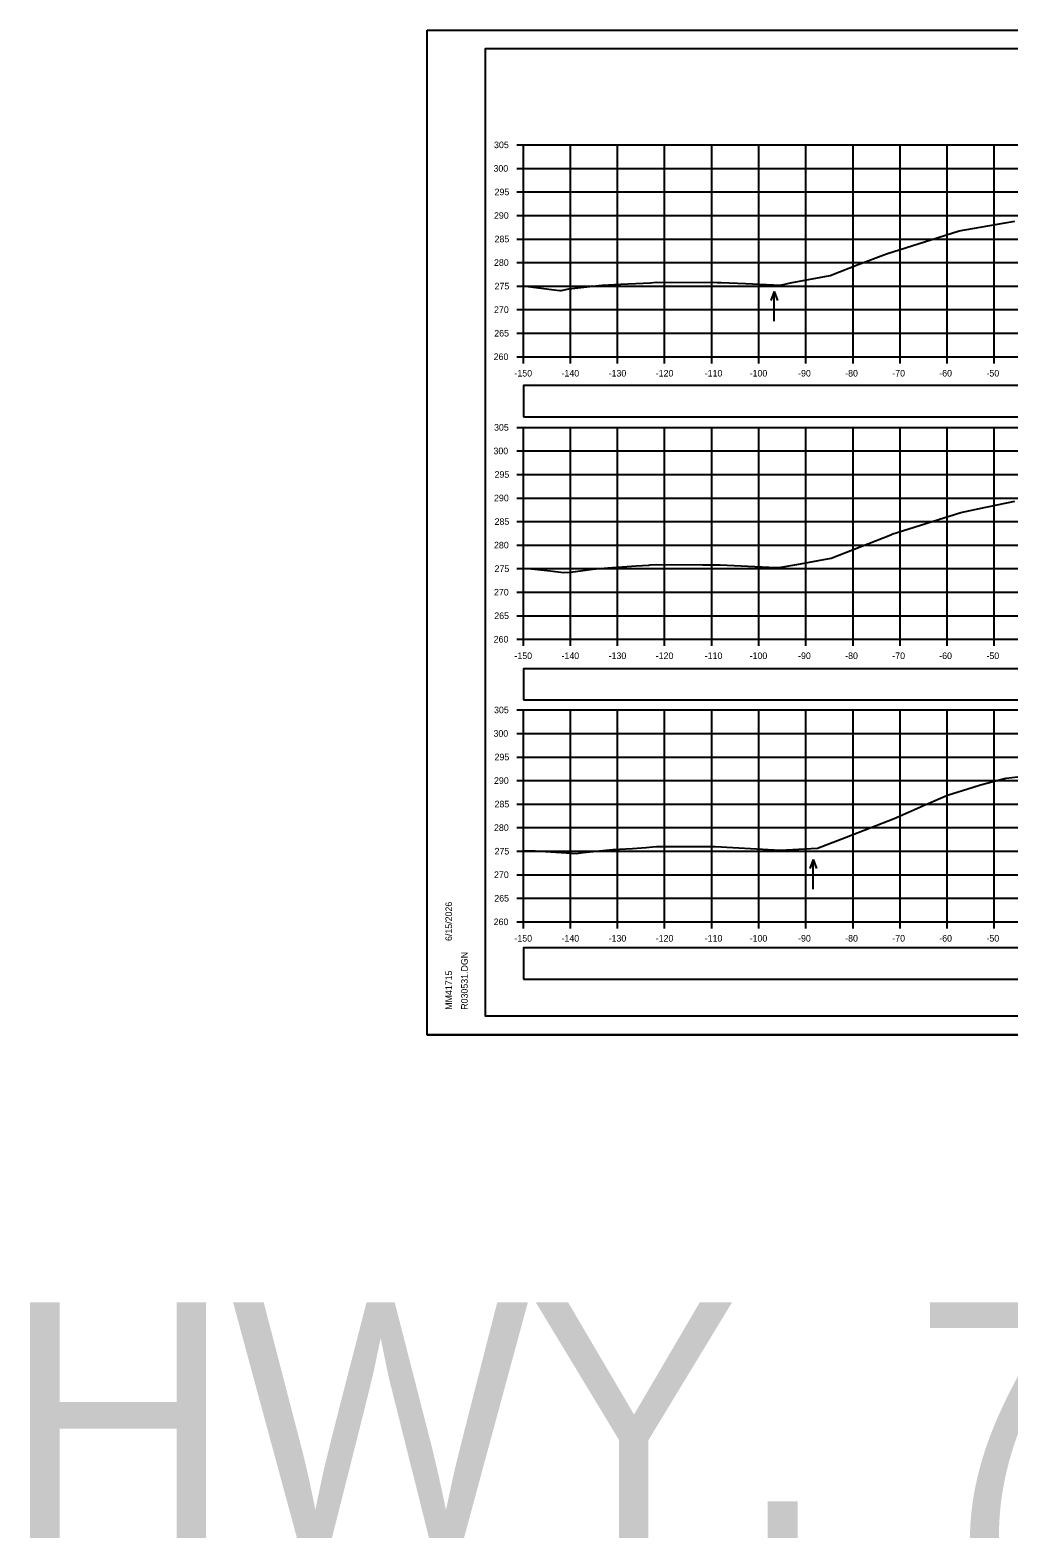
# Model space of a CAD drawing. Extents: x 285 to 4233, y -659 to 3710.
# Drawn here: x 284.6 to 492.4, y -130.7 to 189.5 of the extents above; entities that cross this region are included whole.
import ezdxf

# ---------------------------------------------------------------- set-up
doc = ezdxf.new("R2010")
doc.units = 0
for name, color, linetype in [('R_Axis', 7, 'Continuous'), ('R_Axis Annot', 7, 'Continuous'), ('R_Border', 7, 'Continuous'), ('R_Exist Surface', 7, 'Continuous'), ('R_Grid', 7, 'Continuous'), ('R_No Plot', 7, 'Continuous'), ('R_Water Annot', 7, 'Continuous')]:
    doc.layers.add(name, color=color, linetype=linetype)

msp = doc.modelspace()

# ---------------------------------------------------------------- linework, layer by layer
at = {"layer": 'R_Axis'}
for p, q in [((387.88, 165.15), (389.28, 165.15)), ((389.28, 120.15), (389.28, 165.15)), ((387.88, 160.15), (389.28, 160.15)), ((387.88, 155.15), (389.28, 155.15)), ((387.88, 150.15), (389.28, 150.15)), ((387.88, 145.15), (389.28, 145.15)), ((387.88, 140.15), (389.28, 140.15)), ((387.88, 135.15), (389.28, 135.15)), ((387.88, 130.15), (389.28, 130.15)), ((387.88, 125.15), (389.28, 125.15)), ((387.88, 120.15), (389.28, 120.15)), ((389.28, 120.15), (689.28, 120.15)), ((389.28, 118.75), (389.28, 120.15)), ((399.28, 118.75), (399.28, 120.15)), ((409.28, 118.75), (409.28, 120.15)), ((419.28, 118.75), (419.28, 120.15)), ((429.28, 118.75), (429.28, 120.15)), ((439.28, 118.75), (439.28, 120.15)), ((449.28, 118.75), (449.28, 120.15)), ((459.28, 118.75), (459.28, 120.15)), ((469.28, 118.75), (469.28, 120.15)), ((479.28, 118.75), (479.28, 120.15)), ((489.28, 118.75), (489.28, 120.15)), ((387.88, 105.15), (389.28, 105.15)), ((389.28, 60.15), (389.28, 105.15)), ((387.88, 100.15), (389.28, 100.15)), ((387.88, 95.15), (389.28, 95.15)), ((387.88, 90.15), (389.28, 90.15)), ((387.88, 85.15), (389.28, 85.15)), ((387.88, 80.15), (389.28, 80.15)), ((387.88, 75.15), (389.28, 75.15)), ((387.88, 70.15), (389.28, 70.15)), ((387.88, 65.15), (389.28, 65.15)), ((387.88, 60.15), (389.28, 60.15)), ((389.28, 60.15), (689.28, 60.15)), ((389.28, 58.75), (389.28, 60.15)), ((399.28, 58.75), (399.28, 60.15)), ((409.28, 58.75), (409.28, 60.15)), ((419.28, 58.75), (419.28, 60.15)), ((429.28, 58.75), (429.28, 60.15)), ((439.28, 58.75), (439.28, 60.15)), ((449.28, 58.75), (449.28, 60.15)), ((459.28, 58.75), (459.28, 60.15)), ((469.28, 58.75), (469.28, 60.15)), ((479.28, 58.75), (479.28, 60.15)), ((489.28, 58.75), (489.28, 60.15)), ((387.88, 45.15), (389.28, 45.15)), ((389.28, 0.15), (389.28, 45.15)), ((387.88, 40.15), (389.28, 40.15)), ((387.88, 35.15), (389.28, 35.15)), ((387.88, 30.15), (389.28, 30.15)), ((387.88, 25.15), (389.28, 25.15)), ((387.88, 20.15), (389.28, 20.15)), ((387.88, 15.15), (389.28, 15.15)), ((387.88, 10.15), (389.28, 10.15)), ((387.88, 5.15), (389.28, 5.15)), ((387.88, 0.15), (389.28, 0.15)), ((389.28, 0.15), (689.28, 0.15)), ((389.28, -1.25), (389.28, 0.15)), ((399.28, -1.25), (399.28, 0.15)), ((409.28, -1.25), (409.28, 0.15)), ((419.28, -1.25), (419.28, 0.15)), ((429.28, -1.25), (429.28, 0.15)), ((439.28, -1.25), (439.28, 0.15)), ((449.28, -1.25), (449.28, 0.15)), ((459.28, -1.25), (459.28, 0.15)), ((469.28, -1.25), (469.28, 0.15)), ((479.28, -1.25), (479.28, 0.15)), ((489.28, -1.25), (489.28, 0.15))]:
    msp.add_line(p, q, dxfattribs=at)
at = {"layer": 'R_Axis Annot'}
for points in [[(389.28, 107.36), (516.61, 107.36), (516.61, 114.02), (389.28, 114.02)], [(389.28, 47.26), (516.61, 47.26), (516.61, 53.91), (389.28, 53.91)], [(389.28, -12.05), (516.61, -12.05), (516.61, -5.4), (389.28, -5.4)]]:
    msp.add_lwpolyline(points, close=True, dxfattribs=at)
at = {"layer": 'R_Border'}
for p, q in [((381.28, 185.61), (697.46, 185.61)), ((381.28, -19.85), (381.28, 185.61)), ((381.28, -19.85), (381.28, -19.85)), ((697.46, -19.85), (381.28, -19.85))]:
    msp.add_line(p, q, dxfattribs=at)
at = {"layer": 'R_Exist Surface'}
for points in [[(389.28, 135.14), (389.71, 135.13), (395.79, 134.36), (397.03, 134.22), (397.31, 134.25), (398.95, 134.57), (405.32, 135.28), (406.02, 135.36), (409.99, 135.57), (416.31, 135.88), (417.45, 135.96), (430.46, 135.93), (431.32, 135.93), (436.44, 135.71), (443.87, 135.37), (446.03, 135.82), (454.41, 137.41), (460.4, 139.72), (466.37, 142), (477.33, 145.48), (481.85, 146.88), (491.13, 148.52), (493.61, 148.96)], [(389.28, 75.26), (390.41, 75.21), (395, 74.68), (397.84, 74.31), (399.23, 74.43), (400.35, 74.57), (403.96, 75.01), (407.2, 75.34), (413.23, 75.74), (415.93, 75.9), (416.2, 75.93), (417.5, 76.01), (427.42, 75.99), (431.1, 75.99), (441.41, 75.49), (443.58, 75.37), (447.37, 76.04), (454.65, 77.38), (467.32, 82.36), (467.45, 82.42), (467.52, 82.44), (482.21, 87.06), (486.17, 87.92), (493.65, 89.45)], [(389.28, 15.2), (391.79, 15.19), (398.38, 14.83), (400.48, 14.67), (401.97, 14.84), (408.29, 15.5), (412.43, 15.73), (415.33, 15.91), (416.71, 16.05), (417.57, 16.14), (428.74, 16.17), (430.03, 16.18), (442.55, 15.47), (443.73, 15.4), (445.15, 15.47), (451.72, 15.8), (457.81, 18.11), (468.02, 22.11), (474.74, 25.08), (479.35, 27.03), (484.76, 28.77), (486.32, 29.25), (491.48, 30.58), (491.83, 30.65), (497.84, 31.4)]]:
    msp.add_lwpolyline(points, dxfattribs=at)
at = {"layer": 'R_Grid'}
for p, q in [((389.28, 165.15), (689.28, 165.15)), ((389.28, 120.15), (389.28, 165.15)), ((399.28, 120.15), (399.28, 165.15)), ((409.28, 120.15), (409.28, 165.15)), ((419.28, 120.15), (419.28, 165.15)), ((429.28, 120.15), (429.28, 165.15)), ((439.28, 120.15), (439.28, 165.15)), ((449.28, 120.15), (449.28, 165.15)), ((459.28, 120.15), (459.28, 165.15)), ((469.28, 120.15), (469.28, 165.15)), ((479.28, 120.15), (479.28, 165.15)), ((489.28, 120.15), (489.28, 165.15)), ((389.28, 160.15), (689.28, 160.15)), ((389.28, 155.15), (689.28, 155.15)), ((389.28, 150.15), (689.28, 150.15)), ((389.28, 145.15), (689.28, 145.15)), ((389.28, 140.15), (689.28, 140.15)), ((389.28, 135.15), (689.28, 135.15)), ((389.28, 130.15), (689.28, 130.15)), ((389.28, 125.15), (689.28, 125.15)), ((389.28, 120.15), (689.28, 120.15)), ((389.28, 105.15), (689.28, 105.15)), ((389.28, 60.15), (389.28, 105.15)), ((399.28, 60.15), (399.28, 105.15)), ((409.28, 60.15), (409.28, 105.15)), ((419.28, 60.15), (419.28, 105.15)), ((429.28, 60.15), (429.28, 105.15)), ((439.28, 60.15), (439.28, 105.15)), ((449.28, 60.15), (449.28, 105.15)), ((459.28, 60.15), (459.28, 105.15)), ((469.28, 60.15), (469.28, 105.15)), ((479.28, 60.15), (479.28, 105.15)), ((489.28, 60.15), (489.28, 105.15)), ((389.28, 100.15), (689.28, 100.15)), ((389.28, 95.15), (689.28, 95.15)), ((389.28, 90.15), (689.28, 90.15)), ((389.28, 85.15), (689.28, 85.15)), ((389.28, 80.15), (689.28, 80.15)), ((389.28, 75.15), (689.28, 75.15)), ((389.28, 70.15), (689.28, 70.15)), ((389.28, 65.15), (689.28, 65.15)), ((389.28, 60.15), (689.28, 60.15)), ((389.28, 45.15), (689.28, 45.15)), ((389.28, 0.15), (389.28, 45.15)), ((399.28, 0.15), (399.28, 45.15)), ((409.28, 0.15), (409.28, 45.15)), ((419.28, 0.15), (419.28, 45.15)), ((429.28, 0.15), (429.28, 45.15)), ((439.28, 0.15), (439.28, 45.15)), ((449.28, 0.15), (449.28, 45.15)), ((459.28, 0.15), (459.28, 45.15)), ((469.28, 0.15), (469.28, 45.15)), ((479.28, 0.15), (479.28, 45.15)), ((489.28, 0.15), (489.28, 45.15)), ((389.28, 40.15), (689.28, 40.15)), ((389.28, 35.15), (689.28, 35.15)), ((389.28, 30.15), (689.28, 30.15)), ((389.28, 25.15), (689.28, 25.15)), ((389.28, 20.15), (689.28, 20.15)), ((389.28, 15.15), (689.28, 15.15)), ((389.28, 10.15), (689.28, 10.15)), ((389.28, 5.15), (689.28, 5.15)), ((389.28, 0.15), (689.28, 0.15))]:
    msp.add_line(p, q, dxfattribs=at)
at = {"layer": 'R_No Plot'}
for p, q in [((368.88, 189.51), (702.21, 189.51)), ((368.88, -23.83), (702.21, -23.83))]:
    msp.add_line(p, q, dxfattribs=at)
for points in [[(368.87, 189.51), (702.21, 189.51), (702.21, -23.83), (368.87, -23.83)], [(615.2, 185.61), (634.82, 185.61), (634.82, 175.73), (650.93, 175.73), (674.13, 175.73), (674.25, 147.58), (697.46, 147.58), (697.46, -19.85), (381.28, -19.85), (381.28, 185.61)]]:
    msp.add_lwpolyline(points, close=True, dxfattribs=at)
at = {"layer": 'R_Water Annot'}
for p, q in [((442.54, 134.02), (441.84, 132.09)), ((442.54, 127.73), (442.54, 134.02)), ((442.54, 134.02), (443.24, 132.09)), ((450.8, 13.36), (450.1, 11.44)), ((450.8, 7.08), (450.8, 13.36)), ((450.8, 13.36), (451.5, 11.44))]:
    msp.add_line(p, q, dxfattribs=at)

# ---------------------------------------------------------------- texts
at = {"layer": 'R_Axis Annot'}
for s, p in [('305', (383.06, 164.45)), ('300', (382.94, 159.45)), ('295', (383.17, 154.45)), ('290', (383.05, 149.45)), ('285', (383.17, 144.45)), ('280', (383.05, 139.45)), ('275', (383.17, 134.45)), ('270', (383.05, 129.45)), ('265', (383.11, 124.45)), ('260', (382.98, 119.45)), ('-150', (387.39, 115.95)), ('-140', (397.39, 115.95)), ('-130', (407.39, 115.95)), ('-120', (417.39, 115.95)), ('-110', (427.79, 115.95)), ('-100', (437.33, 115.95)), ('-90', (447.62, 115.95)), ('-80', (457.62, 115.95)), ('-70', (467.62, 115.95)), ('-60', (477.59, 115.95)), ('-50', (487.62, 115.95)), ('305', (383.06, 104.45)), ('300', (382.94, 99.45)), ('295', (383.17, 94.45)), ('290', (383.05, 89.45)), ('285', (383.17, 84.45)), ('280', (383.05, 79.45)), ('275', (383.17, 74.45)), ('270', (383.05, 69.45)), ('265', (383.11, 64.45)), ('260', (382.98, 59.45)), ('-150', (387.39, 55.95)), ('-140', (397.39, 55.95)), ('-130', (407.39, 55.95)), ('-120', (417.39, 55.95)), ('-110', (427.79, 55.95)), ('-100', (437.33, 55.95)), ('-90', (447.62, 55.95)), ('-80', (457.62, 55.95)), ('-70', (467.62, 55.95)), ('-60', (477.59, 55.95)), ('-50', (487.62, 55.95)), ('305', (383.06, 44.45)), ('300', (382.94, 39.45)), ('295', (383.17, 34.45)), ('290', (383.05, 29.45)), ('285', (383.17, 24.45)), ('280', (383.05, 19.45)), ('275', (383.17, 14.45)), ('270', (383.05, 9.45)), ('265', (383.11, 4.45)), ('260', (382.98, -0.55)), ('-150', (387.39, -4.05)), ('-140', (397.39, -4.05)), ('-130', (407.39, -4.05)), ('-120', (417.39, -4.05)), ('-110', (427.79, -4.05)), ('-100', (437.33, -4.05)), ('-90', (447.62, -4.05)), ('-80', (457.62, -4.05)), ('-70', (467.62, -4.05)), ('-60', (477.59, -4.05)), ('-50', (487.62, -4.05))]:
    msp.add_text(s, height=1.4, dxfattribs=at).set_placement(p)
at = {"layer": 'R_Border'}
for s, p in [('6/15/2026', (374.14, -3.92)), ('R030531.DGN', (377.47, -18.52)), ('MM41715', (374.14, -18.52))]:
    msp.add_text(s, height=1.4, rotation=90, dxfattribs=at).set_placement(p)
at = {"layer": 'R_No Plot'}
msp.add_text('HWY. 71 LT.', height=50, dxfattribs=at).set_placement((279.07, -130.67))

doc.saveas('drawing.dxf')
